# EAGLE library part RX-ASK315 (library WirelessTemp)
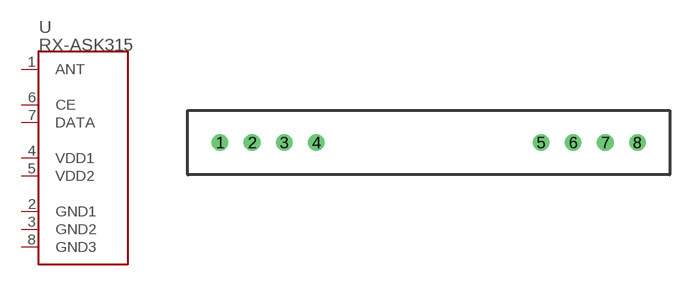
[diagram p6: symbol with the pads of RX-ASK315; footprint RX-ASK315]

Designator prefix U

## RX-ASK315  [RX-ASK315]
1  ANT  pas
2  GND1  pwr
3  GND2  pwr
4  VDD1  pwr
5  VDD2  pwr
6  CE  in
7  DATA  out
8  GND3  pwr

## Footprint RX-ASK315 (pad centres in mm)
drill 0.8 round: 1 -12.7,-2.54; 2 -10.16,-2.54; 3 -7.62,-2.54; 4 -5.08,-2.54; 5 12.7,-2.54; 6 15.24,-2.54; 7 17.78,-2.54; 8 20.32,-2.54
